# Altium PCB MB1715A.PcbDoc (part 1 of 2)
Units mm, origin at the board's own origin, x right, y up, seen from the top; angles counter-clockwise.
Board outline 74 x 57 mm, 2 copper layers (Top Layer, Bottom Layer), stack 1.646 mm thick; 54 components, 56 nets, 204 pads, 1587 vias.
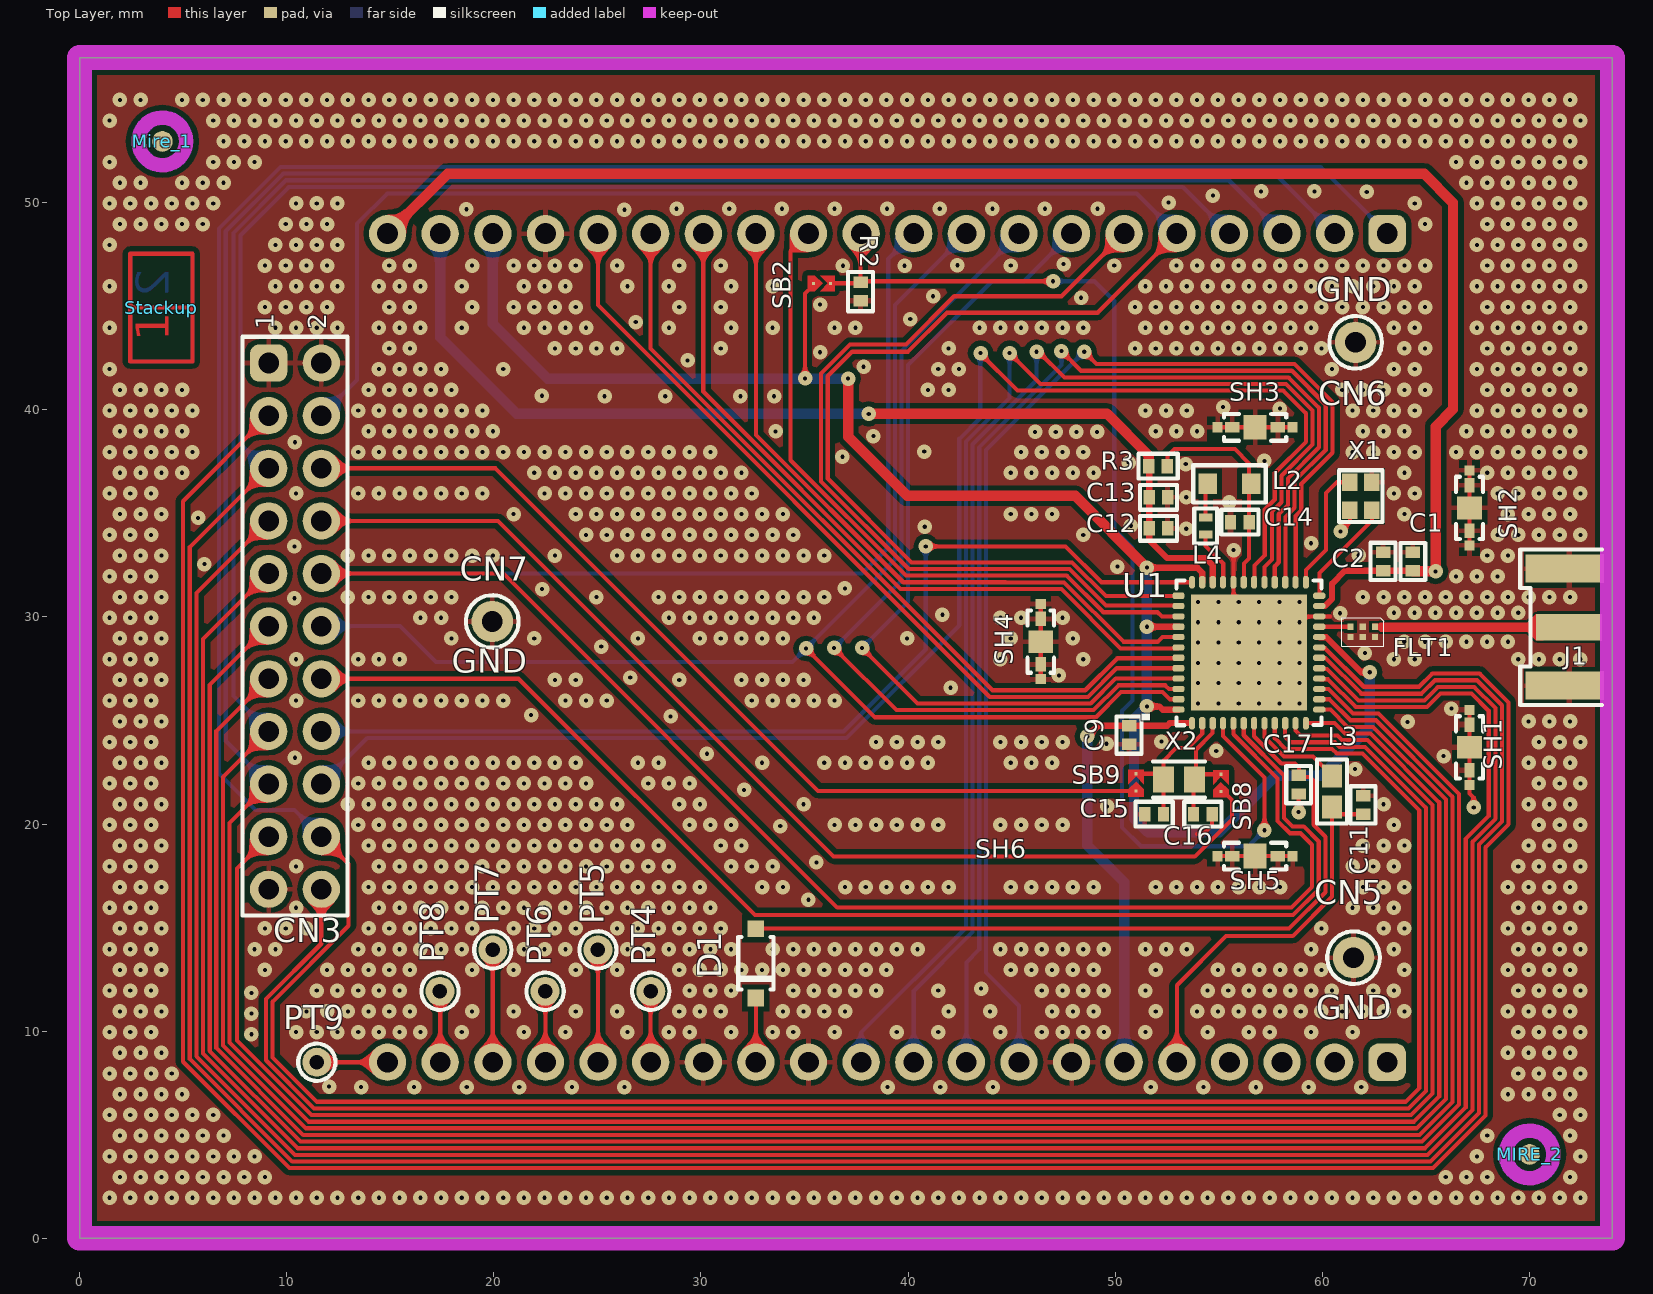
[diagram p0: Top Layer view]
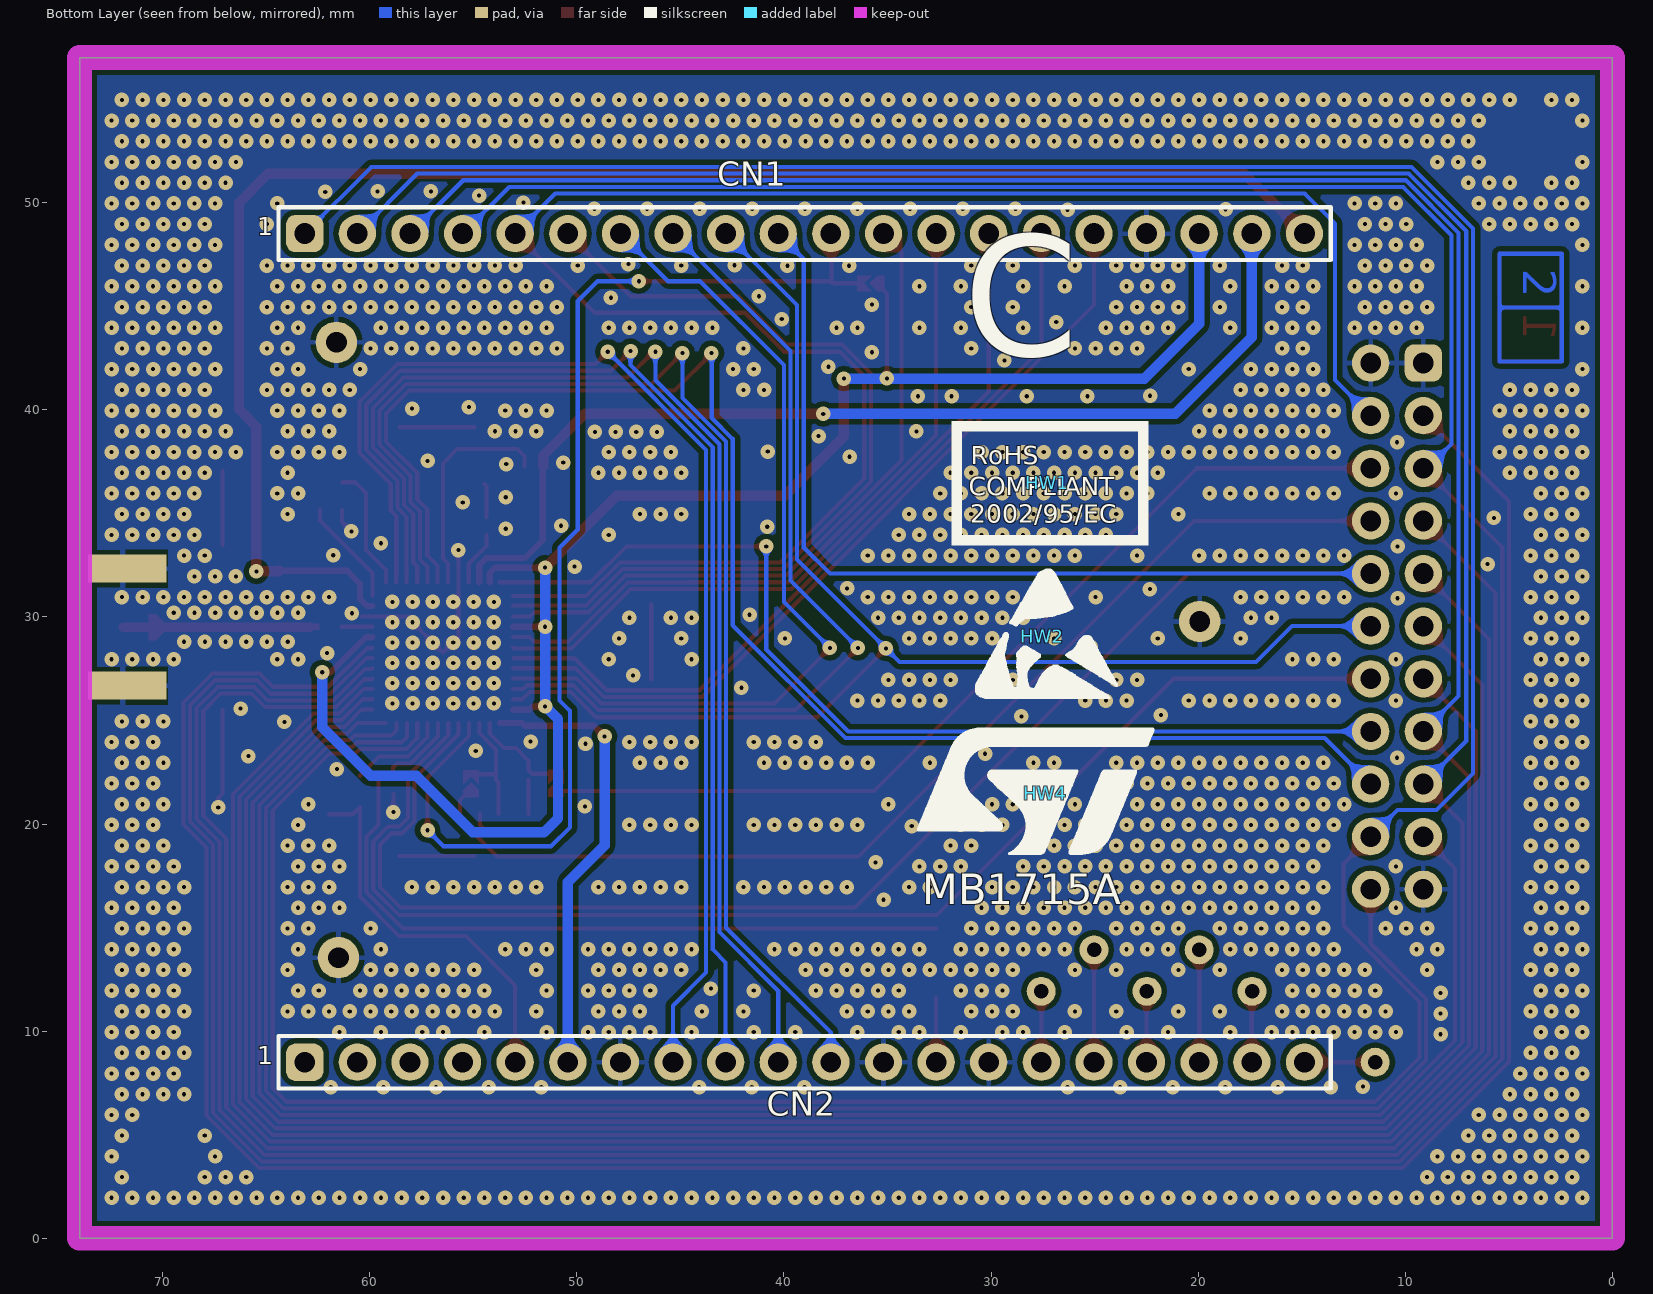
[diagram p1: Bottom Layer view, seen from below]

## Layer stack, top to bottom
Top Solder: solder mask 0.03, Solder Resist, Dk 3.6
Top Layer: signal copper 0.048
Dielectric 1: core 1.55, Dk 4.5
Bottom Layer: signal copper 0.048
Bottom Solder: solder mask 0.03, Solder Resist, Dk 3.6

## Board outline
0,0 74,0 74,57 0,57 0,56.95

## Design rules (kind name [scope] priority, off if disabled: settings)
BoardOutlineClearance [All] p1 off: gap=0.6 ignorepadtopadclearanceinfootprint=FALSE
Clearance Clearance_SB [(ObjectKind = 'Region') and InComponent('SB*') vs (ObjectKind = 'Region') and InComponent('SB*')] p1: gap=0.15 ignorepadtopadclearanceinfootprint=TRUE
Clearance Clearance_FLT1_6 [InNet('NetFLT1_6') vs InNet('GND')] p2: gap=0.106 ignorepadtopadclearanceinfootprint=TRUE except(0.15: Arc-SMDPad Track-SMDPad SMDPad-SMDPad SMDPad-THPad SMDPad-Via SMDPad-Fill SMDPad-Poly SMDPad-Region SMDPad-Text SMDPad-Hole)
Clearance Clearance_FLT1_5 [InNet('NetFLT1_5') vs InNet('GND')] p3: gap=0.104 ignorepadtopadclearanceinfootprint=TRUE except(0.15: Arc-SMDPad Track-SMDPad SMDPad-SMDPad SMDPad-THPad SMDPad-Via SMDPad-Fill SMDPad-Poly SMDPad-Region SMDPad-Text SMDPad-Hole)
Clearance Clearance_Tab [(ObjectKind = 'Pad') And (Name Like 'Tab*-*') vs OnLayer('Keep-Out Layer')] p4: gap=0 ignorepadtopadclearanceinfootprint=TRUE
Clearance Clearance_via_to_via [(ObjectKind = 'Via') And (Net <> 'GND') vs (ObjectKind = 'Via') And (Net <> 'GND')] p5 off: gap=0.65 ignorepadtopadclearanceinfootprint=TRUE
Clearance "Clearance_Polygon to All" [InPoly] p6: gap=0.25 ignorepadtopadclearanceinfootprint=TRUE
Clearance "Clearance_VIA to PAD" [IsVia vs ISPAD] p7: gap=0.25 ignorepadtopadclearanceinfootprint=TRUE
Clearance [All] p8: gap=0.12 ignorepadtopadclearanceinfootprint=TRUE except(0.2: Arc-Fill Arc-Poly Arc-Region Track-Fill Track-Poly Track-Region SMDPad-Fill SMDPad-Poly SMDPad-Region THPad-Fill THPad-Poly THPad-Region Via-Fill Via-Poly Via-Region Fill-Fill Fill-Poly Fill-Region Poly-Poly Poly-Region Region-Region; 0.25: Arc-Via Track-Via SMDPad-Via THPad-Via)
ComponentClearance ComponentClearance_Blindage [InComponent('SH1')    or InComponent('SH2')            or InComponent('SH3')               or InComponent('SH4')           or InComponent('SH5') vs InComponent('SH6')] p1: gap=0 collisioncheckmode=3 verticalgap=0 showdistances=FALSE
ComponentClearance [All] p2: gap=0 collisioncheckmode=3 verticalgap=0.1 showdistances=FALSE
HoleSize [All] p1: absolutevalues=TRUE maxlimit=10 minlimit=0.025 maxpercent=80.000 minpercent=20.000
MaximumViaCount [All] p1: limit=3
MinimumSolderMaskSliver [All] p1: minsoldermaskwidth=0.1
PlaneConnect [InNet('GND')] p1: planeconnectstyle=Relief reliefexpansion=0.508 reliefentries=4 reliefconductorwidth=0.21 reliefairgap=0.21
PolygonConnect PolygonConnect_FLT1 [HasFootprint('IPD') vs InNet('GND')] p1: connectstyle=Direct reliefconductorwidth=0.254 reliefentries=4 polygonreliefangle="90 Angle" airgapwidth=0.254
PolygonConnect PolygonConnect_All [All] p2: thpad.connectstyle=Relief thpad.reliefconductorwidth=0.25 thpad.reliefentries=4 thpad.polygonreliefangle="90 Angle" thpad.airgapwidth=0.25 smdpad.connectstyle=Relief smdpad.reliefconductorwidth=0.25 smdpad.reliefentries=4 smdpad.polygonreliefangle="90 Angle" smdpad.airgapwidth=0.25 via.connectstyle=Direct via.reliefconductorwidth=0.2 via.reliefentries=4 via.polygonreliefangle="90 Angle" via.airgapwidth=0.25
RoutingVias [All] p1: holewidth=0.2 width=0.7 viastyle="Through Hole" minholewidth=0.2 minwidth=0.7 maxholewidth=0.2 maxwidth=0.7
ShortCircuit ShortCircuit_U1 [(ObjectKind = 'Pad') And (Name = 'U1-49') vs IsVia and InNet('GND')] p1: allowed=TRUE
ShortCircuit [All] p2: allowed=FALSE
SilkToSilkClearance [All] p1: silktosilkclearance=0.2
SilkToSolderMaskClearance [IsPad] p1: minsilkscreentomaskgap=0.2 clearancetoexposedcopper=TRUE
SolderMaskExpansion SolderMaskExpansion_VIA [IsVia] p1: expansion=-0.2 istentingtop=FALSE
SolderMaskExpansion [All] p2: expansion=0.1 istentingtop=FALSE
Width Width_Antenna [InNetClass('50ohm')] p1: maxlimit=0.45 minlimit=0.2 preferedwidth=0.45
Width [All] p2: maxlimit=1.5 minlimit=0.2 preferedwidth=0.2 minimp=50.000000 maximp=50.000000 favimp=50.000000
23 further rules are at their usual default settings.

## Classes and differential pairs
component class MB1715A: C1 C2 C9 C11 C12 C13 C14 C15 C16 C17 CN1 CN2 CN3 CN5 CN6 CN7 D1 FLT1 J1 L2 L3 L4 PT4 PT5 PT6 PT7 PT8 PT9 R2 R3 SB2 SB8 SB9 SH1 SH2 SH3 SH4 SH5 SH6 U1 X1 X2

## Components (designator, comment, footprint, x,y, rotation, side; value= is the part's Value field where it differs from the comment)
C1 "" CAPC1005X06N 64.361,32.67 r270 top value=100nF
C2 "" CAPC1005X06N 62.925,32.675 r270 top value=100pF
C9 "" CAPC1005X06N 50.661,24.294 r90 top value=100nF
C11 "" CAPC1005X06N 61.961,20.92 r270 top value=100nF
C12 "" CAPC1005X06N 52.087,34.27 r0 top value=4.7uF
C13 "" CAPC1005X06N 52.086,35.77 r180 top value=100nF
C14 "" CAPC1005X06N 56.011,34.57 r180 top value=4.7uF
C15 "" CAPC1005X06N 51.875,20.475 r180 top value=15pF
C16 "" CAPC1005X06N 54.225,20.475 r0 top value=15pF
C17 "" CAPC1005X06N 58.85,21.9 r90 top value=100nF
Cartridge "Comment" "CARTRIDGE ST GRENOBLE-L2" 157.458,-59.293 r0 top
CARTRIDGE "Comment" "CARTRIDGE_B ST Grenoble" -119.542,-59.293 r180 bottom
CN1 "CON20" CO_SAMTEC_TSW-120-07-x-S 39,48.5 r180 bottom locked
CN2 "CON20" CO_SAMTEC_TSW-120-07-x-S 39,8.5 r180 bottom locked
CN3 "HEADER 11X2 Male" CO_SAMTEC_TSW-111-07-x-D 10.4,29.55 r270 top
CN5 "HEADER_1X1" TP_KEYSTONE_5001 61.5,13.55 r90 top
CN6 "HEADER_1X1" TP_KEYSTONE_5001 61.6,43.25 r90 top
CN7 "HEADER_1X1" TP_KEYSTONE_5001 19.925,29.775 r90 top
D1 "BAT54Z" SOD123_KA 32.65,13.275 r270 top
FLT1 "IPD" IPD 61.946,29.27 r270 top
HW1 "Logo" LOGO_ROHS 27.275,36.475 r180 bottom value="LOGO ROHS"
HW2 "Logo" LOGO_MAIN 27.525,29.075 r180 bottom value="LOGO ESD"
HW4 "Logo" LOGO_ST 27.375,21.475 r180 bottom value="LOGO ST"
J1 "SMA_T_9.52_NF" SAMTEC_SMA-J-P-H-ST-EM1 74,29.5 r90 top
L2 "10uH - LQM21FN100M70L" IND_MURATA_0805 55.511,36.42 r0 top value=10uH
L3 "" INDC1608X95N 60.461,21.57 r90 top value=600R@100MHz
L4 "10nH - LQG15WZ10NJ02D" IND_MURATA_0402 54.362,34.383 r270 top value=10nH
M1 "Comment" "MIRE PCB" 89,28.55 r0 top
M2 "Comment" "MIRE PCB" -10,-14.95 r0 top
M3 "Comment" "MIRE PCB" 37,75.05 r0 top
MASTER "Comment" "Design Information V2 Rigid" -19.542,130.707 r0 top
Mire_1 "Comment" MIRE 4,52.95 r0 top
MIRE_2 "Comment" MIRE 70,4.05 r0 top
PT4 "PT" TP140x70H 27.575,11.925 r0 top
PT5 "PT" TP140x70H 25.025,13.925 r0 top
PT6 "PT" TP140x70H 22.475,11.925 r0 top
PT7 "PT" TP140x70H 19.95,13.925 r0 top
PT8 "PT" TP140x70H 17.4,11.925 r0 top
PT9 "PT" TP140x70H 11.455,8.5 r0 top
R2 "Resistor" RESC1005X04N 37.7,45.7 r270 top value=10k
R3 "Resistor" RESC1005X04N 52.061,37.27 r0 top value=0ohm
SB2 "Open" GC_0402 35.8,46.1 r0 top
SB8 "Open" GC_0402 55.1,21.95 r90 top
SB9 "Open" GC_0402 51,21.975 r90 top
SH1 "S0951-46R" SHIELD_HARWIN_S0951-46R 67.1,23.7 r90 top
SH2 "S0951-46R" SHIELD_HARWIN_S0951-46R 67.1,35.26 r90 top
SH3 "S0951-46R" SHIELD_HARWIN_S0951-46R 56.75,39.15 r180 top
SH4 "S0951-46R" SHIELD_HARWIN_S0951-46R 46.4,28.8 r90 top
SH5 "S0951-46R" SHIELD_HARWIN_S0951-46R 56.75,18.45 r180 top
SH6 "36003200S" SHIELD_WURTH_36003200S 56.75,28.8 r0 top
Stackup "Comment" "Stackup 2L" 3.95,44.925 r90 top
U1 "STM32WB15_QFN48" STM32WBXX_QFN48 56.45,28.27 r90 top
X1 "NX2016_32M" OSC_NDK_NX2016SA 61.85,35.825 r270 top value="32 MHz"
X2 "NX2012_32K768" OSC_NDK_NX2012SA 53.075,22.15 r0 top value="32.768 KHz"

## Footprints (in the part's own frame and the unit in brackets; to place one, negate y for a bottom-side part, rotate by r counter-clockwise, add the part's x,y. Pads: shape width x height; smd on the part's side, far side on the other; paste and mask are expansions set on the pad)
CAPC1005X06N [mm] "Chip Capacitor, 2-Leads, Body 1.00x0.50x0.60mm (0402)"
  rect 0.55x0.7 smd: 1(-0.45,0) 2(0.45,0)
  silkscreen extent -0.9,-0.6 0.9,0.6, body extent -0.5,-0.25 0.5,0.25, height 0.6
"CARTRIDGE ST GRENOBLE-L2" [mil] "Technical drawing cartridge - Created : 2020-07-28 by Polygone CAO"
  round 20 on Mech16: 1(-6054.21,346.77)
"CARTRIDGE_B ST Grenoble" [mil] "Technical drawing cartridge bottom- Created : 2020-05-12 by Polygone CAO"
  round 20 on Mech16: 1(-6054.21,346.77)
CO_SAMTEC_TSW-111-07-x-D [mm] "Header, 2x11-Leads, 27.94x5.08x10.80mm, Pitch 2.54x2.54mm"
  rrect50% 1.8x1.8 hole 1: 1(-12.7,-1.27)
  round 1.8 hole 1: 2(-12.7,1.27) 3(-10.16,-1.27) 4(-10.16,1.27) 5(-7.62,-1.27) 6(-7.62,1.27) 7(-5.08,-1.27) 8(-5.08,1.27) 9(-2.54,-1.27) 10(-2.54,1.27) 11(0,-1.27) 12(0,1.27) 13(2.54,-1.27) 14(2.54,1.27) 15(5.08,-1.27) 16(5.08,1.27) 17(7.62,-1.27) 18(7.62,1.27) 19(10.16,-1.27) 20(10.16,1.27) 21(12.7,-1.27) 22(12.7,1.27)
  silkscreen extent -13.97,-2.54 13.97,2.54, body extent -13.97,-2.54 13.97,2.54, height 8.38
CO_SAMTEC_TSW-120-07-x-S [mm] "Header, 20-Leads, 50.80x2.54x10.80mm, Pitch 2.54mm"
  rrect50% 1.8x1.8 hole 1: 1(-24.13,0)
  round 1.8 hole 1: 2(-21.59,0) 3(-19.05,0) 4(-16.51,0) 5(-13.97,0) 6(-11.43,0) 7(-8.89,0) 8(-6.35,0) 9(-3.81,0) 10(-1.27,0) 11(1.27,0) 12(3.81,0) 13(6.35,0) 14(8.89,0) 15(11.43,0) 16(13.97,0) 17(16.51,0) 18(19.05,0) 19(21.59,0) 20(24.13,0)
  silkscreen extent -25.4,-1.27 25.4,1.27, body extent -25.46,-1.27 25.46,1.27, height 8.38
"Design Information V2 Rigid" [mm] "Design Information PCB Rigid - Last Update : 2019-22-10  by Polygone CAO"
GC_0402 [mm] "Grain de café format 0402"
  rect 0.15x0.15 smd paste-1: 1(-0.375,0) 2(0.45,0)
  Top Layer region: -0.05,0.375 0.65,0.375 0.65,-0.375 -0.05,-0.375 0.325,0
  Top Layer region: -0.65,0.375 -0.3,0.375 0.075,0 -0.3,-0.375 -0.65,-0.375
IND_MURATA_0402 [mm] "Wire Wound Ceramic Inductor 2-Leads, Body 1.10x0.56x0.60mm (max), Pitch 0.825mm"
  rect 0.375x0.65 smd: 1(-0.412,0) 2(0.413,0)
  silkscreen extent -0.85,-0.55 0.85,0.55, body extent -0.5,-0.27 0.5,0.28, height 0.5
IND_MURATA_0805 [mm] "Wire Wound Ceramic Inductor 2-Leads, Body 2.20x1.27x1.45mm (max), Pitch 2.10mm"
  rect 0.9x1 smd: 1(-1.05,0) 2(1.05,0)
  silkscreen extent -1.75,-0.9 1.75,0.9, body extent -1,-0.6 1,0.6, height 0.95
INDC1608X95N [mm] "Chip Inductor, 2-Leads, Body 1.75x0.95x0.95mm (0603)"
  rect 1.1x0.95 smd: 1(-0.75,0) 2(0.75,0)
  silkscreen extent -1.55,-0.73 1.55,0.73, body extent -0.8,-0.48 0.8,0.48, height 0.8
IPD [mm]
  rect 0.3x0.3 smd paste-0.05 mask-0.05: 1(0.25,-0.587) 2(0.25,0) 3(0.25,0.587) 4(-0.25,0) 5(-0.25,-0.587) 6(-0.25,0.587)
  silkscreen extent -0.68,-1.02 0.68,1.01, body extent -0.68,-1.02 0.68,1.02, height 0.54
LOGO_MAIN [mm]
  silkscreen extent -3.24,-3.02 3.65,3.22
LOGO_ROHS [mm]
  silkscreen extent -4.63,-3.02 4.87,2.98
LOGO_ST [mm]
  silkscreen extent -6.18,-2.95 5.25,3.14
MIRE [mm] "Fiducial Target Round , Pad 1.0mm, Keepout 3mm"
  round 1 smd mask+1: 1(0,0)
  Top Layer keep-out circle w0.7: c0,0 r1.15
  body extent -0.5,-0.5 0.5,0.5, height 0.04
"MIRE PCB" [mm]
OSC_NDK_NX2012SA [mm] "Crystal, 2-Leads, Body 2.05x1.20x0.55mm (Tol:-/+0.05)"
  rect 1x1.25 smd: 1(-0.75,0) 2(0.75,0)
  silkscreen extent -1.25,-0.87 1.25,0.87, body extent -1.04,-0.63 1.03,0.63, height 0.55
OSC_NDK_NX2016SA [mm] "Crystal, 4-Leads, Body 2.10x1.61x0.50mm (max), Pitch 1.35x1.05mm"
  rect 0.85x0.75 smd: 1(-0.675,-0.525) 2(0.675,-0.525) 3(0.675,0.525) 4(-0.675,0.525)
  silkscreen extent -1.25,-1.05 1.25,1.05, body extent -1,-0.8 1,0.8, height 0.5
RESC1005X04N [mm] "Chip Resistor, 2-Leads, Body 1.00x0.50mm (0402)"
  rect 0.55x0.7 smd: 1(-0.45,0) 2(0.45,0)
  silkscreen extent -0.95,-0.6 0.95,0.6, body extent -0.5,-0.25 0.5,0.25, height 0.35
SAMTEC_SMA-J-P-H-ST-EM1 [mm] "SMA Edge Mount Receptacle 50Ohm Horizontal, 5-Leads, Body 6.35x13.33x3.68mm, pitch 2.825mm"
  rect 1.27x3.2 smd: 1(0,2.1)
  rect 1.35x3.8 smd: 2(-2.825,2.3) 2(2.825,2.3)
  rect 1.35x3.8 smd far side: 2(-2.825,2.3) 2(2.825,2.3)
  silkscreen extent -3.75,0.5 3.75,4.45, body extent -3.17,-10.13 3.17,3.2, height 3.8
SHIELD_HARWIN_S0951-46R [mm] "Shield Clip, Body 3.90x1.10x1.28mm"
  rect 0.48x0.5 smd: 1(-1.81,0) 1(1.81,0)
  rect 0.7x0.5 smd: 1(-1.1,0) 1(1.1,0)
  rect 1.1x1.2 smd: 1(0,0)
  silkscreen extent -1.5,-0.65 1.5,0.65, body extent -1.95,-0.55 1.95,0.55, height 1.28
SHIELD_WURTH_36003200S [mm] "Shielding Cabinet, Body 20.90x20.90x3.20mm"
  body extent -10.45,-10.45 10.45,10.45, height 3.7
SOD123_KA [mm] "SOD-123, 2 Leads, Body 2.85x1.70x1.45mm"
  rect 0.8x0.8 smd: A(-1.675,0) K(1.675,0)
  silkscreen extent -1.27,-0.85 1.27,0.85, body extent -1.85,-0.8 1.85,0.8, height 1.27
"Stackup 2L" [mm] "Stackup 2 Layers"
  Top Layer lines w0.2: 0,1.5 0,-1.5 ; -2.6,1.5 2.6,1.5 2.6,-1.5 -2.6,-1.5 -2.6,1.5
  Bottom Layer lines w0.2: 0,1.5 2.6,1.5 2.6,-1.5 0,-1.5 ; 0,1.5 -2.6,1.5 -2.6,-1.5 0,-1.5 ; 0,1.5 0,-1.5
STM32WBXX_QFN48 [mm] "QFN48 7x7x0.55mm pitch 0.5mm"
  oct 0.6x0.3 smd: 1(-3.398,2.75) 2(-3.398,2.25) 3(-3.398,1.75) 4(-3.398,1.25) 5(-3.398,0.75) 6(-3.398,0.25) 7(-3.398,-0.25) 8(-3.398,-0.75) 9(-3.398,-1.25) 10(-3.398,-1.75) 11(-3.398,-2.25) 12(-3.398,-2.75) 25(3.398,-2.75) 26(3.398,-2.25) 27(3.398,-1.75) 28(3.398,-1.25) 29(3.398,-0.75) 30(3.398,-0.25) 31(3.398,0.25) 32(3.398,0.75) 33(3.398,1.25) 34(3.398,1.75) 35(3.398,2.25) 36(3.398,2.75)
  oct 0.3x0.6 smd: 13(-2.75,-3.398) 14(-2.25,-3.398) 15(-1.75,-3.398) 16(-1.25,-3.398) 17(-0.75,-3.398) 18(-0.25,-3.398) 19(0.25,-3.398) 20(0.75,-3.398) 21(1.25,-3.398) 22(1.75,-3.398) 23(2.25,-3.398) 24(2.75,-3.398) 37(2.75,3.398) 38(2.25,3.398) 39(1.75,3.398) 40(1.25,3.398) 41(0.75,3.398) 42(0.25,3.398) 43(-0.25,3.398) 44(-0.75,3.398) 45(-1.25,3.398) 46(-1.75,3.398) 47(-2.25,3.398) 48(-2.75,3.398)
  rect 5.6x5.6 smd paste-3: 49(0,0)
  silkscreen extent -3.5,-3.5 3.49,3.5, body extent -3.51,-3.51 3.51,3.51, height 0.78
TP140x70H [mm] "Test Point, 1-Lead, Pad size 1.4mm x Hole 0.7mm"
  round 1.4 hole 0.7: 1(0,0)
  silkscreen extent -0.9,-0.9 0.9,0.9, body extent -0.7,-0.7 0.7,0.7, height 0.04
TP_KEYSTONE_5001 [mm] "MultiPurpose THM Test Point, 1-Lead, Body D2.54x4.57mm"
  round 2 hole 1: 1(0,0)
  silkscreen extent -1.27,-1.27 1.27,1.27, body extent -1.27,-1.27 1.27,1.27, height 4.57

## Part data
C1 C9 C11 C13 C17: library part MCD-00102, "Capacitor, MLCC, 100nF, 16V, X7R, 10%, 0402, T=0,5mm", Manufacturer=YAGEO, Manufacturer_Part_Number=CC0402KRX7R7BB104, Package=C0402
C2: library part MCD-00102, "Capacitor, MLCC, 100pF, 50V, C0G, 5%, 0402, T=0,5mm", Manufacturer=YAGEO, Manufacturer_Part_Number=CC0402JRNPO9BN101, Package=C0402
C12 C14: library part MCD-00102, "Capacitor, MLCC, 4.7uF, 10V, X5R, 10%, 0402, T=0,5mm", Manufacturer=TDK, Manufacturer_Part_Number=C1005X5R1A475K050BC, Package=C0402
C15 C16: library part MCD-00102, "Capacitor, MLCC, 4.3pF, 50V, C0G, ±0.1pF, 0402, T=0,5mm", Manufacturer=KEMET, Manufacturer_Part_Number=C0402C439B5GACTU, Package=C0402
CN1 CN2: "Connector right-angle, pitch 2.54mm, 20 contacts", Manufacturer=SAMTEC, Manufacturer_Part_Number=TSW-120-07-L-S
CN3: library part "HEADER 11X2", "Connector right-angle, pitch 2.54mm, 2x11 contacts", Manufacturer=SAMTEC, Manufacturer_Part_Number=TSW-111-07-L-D
CN5 CN6 CN7: "PC Test point miniature - Black", Manufacturer=KEYSTONE, Manufacturer_Part_Number=5001
D1: library part BAT54K, "Schottky Diode", Manufacturer=STMICROELECTRONICS, Manufacturer_Part_Number=BAT54ZFILM
HW1: library part MCD-00628, "\"ROHS\" logo footprint for PCB"
HW2: library part MCD-00627, "\"Hand\" ESD logo footprint for PCB"
HW4: library part MCD-00625, "\"STMicroelectronics\" logo footprint for PCB"
J1: "SMA Jack, Edge Mount, 50 Ohms", Manufacturer=SAMTEC, Manufacturer_Part_Number=SMA-J-P-H-ST-EM1
L2: library part IND_LQM21FN100M70L, "Inductor, 10uH, 20%, 100mA, 0805", Manufacturer=Murata, Manufacturer_Part_Number=LQM21FN100M70L
L3: library part MCD-00047, "SMD Chip ferrite bead, 600R@100MHz +/-25%, 350mA, 500mohm DC, 0603, T=0.8mm", Manufacturer=TAI-TECH, Manufacturer_Part_Number=FCM1608KF-601T03
L4: library part IND_LQM21FN100M70L, "Inductor, 10nH, 5%, 500mA, 0402", Manufacturer=Murata, Manufacturer_Part_Number=LQG15WZ10NJ02D
PT4 PT5 PT6 PT7 PT8 PT9: "Point de test PCB"
R2: library part RES, "Resistor,10K,0402,1%,1/10W", Manufacturer=VISHAY, Manufacturer_Part_Number=MCS04020C1002FE000
R3: library part RES, "Resistor,0ohm,0402,1/10W"
SB2 SB8 SB9: library part Strap2, "Solder Jumper - Open"
SH1 SH2 SH3 SH4 SH5: library part EMI_WURTH_36103255, "Shield clips S0951-46R", Case=SMD, Manufacturer=Harwin, Operating Temp. Range=I_-40/+125°C
SH6: library part EMI_WURTH_36003250, "WE-SHC Shielding Cover 20x20mm - SMD", Case=SMD, Manufacturer=Wurth, Operating Temp. Range=I_-40/+125°C
X1: "Crystal 32 MHz, 8pF, -+10 PPM, R=60Ω, SMD", Manufacturer=NDK, Manufacturer_Part_Number="NX2016SA 32 MHz EXS00A-CS06654"
X2: "Crystal NDK 2.0x1.2mm  32.768 KHz", Manufacturer=NDK, Manufacturer_Part_Number="NX2012SA 32.768KHz  EXS00A-MU00389"

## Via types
v1: diameter 0.7, hole 0.2, Top Layer to Bottom Layer, 1587 vias

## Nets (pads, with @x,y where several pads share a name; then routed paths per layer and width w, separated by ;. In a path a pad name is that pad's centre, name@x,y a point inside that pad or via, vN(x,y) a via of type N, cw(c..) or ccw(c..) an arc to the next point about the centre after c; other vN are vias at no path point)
AT0: CN2.8 U1.26 | length 59.4
  Top Layer w0.2: v1(48.5,42.8) 49.1,42.2 58.653,42.2 60.48,40.373 60.48,37.92 58.975,36.415 58.975,35.134 58.712,34.871 U1.26@58.712,31.669
  Bottom Layer w0.2: CN2.8@45.35,8.5 45.35,11.225 43.75,12.825 43.75,38.05 v1(48.5,42.8)
AT1: CN2.9 U1.27 | length 59.4
  Top Layer w0.2: v1(47.4,42.827) v1(47.4,42.827) 48.345,41.88 58.52,41.88 60.16,40.24 60.16,38.052 58.655,36.547 58.655,35.266 58.212,34.823 U1.27@58.212,31.669
  Bottom Layer w0.2: CN2.9@42.81,8.5 42.81,13.315 43.43,13.935 43.43,38.183 47.4,42.153 v1(47.4,42.827)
